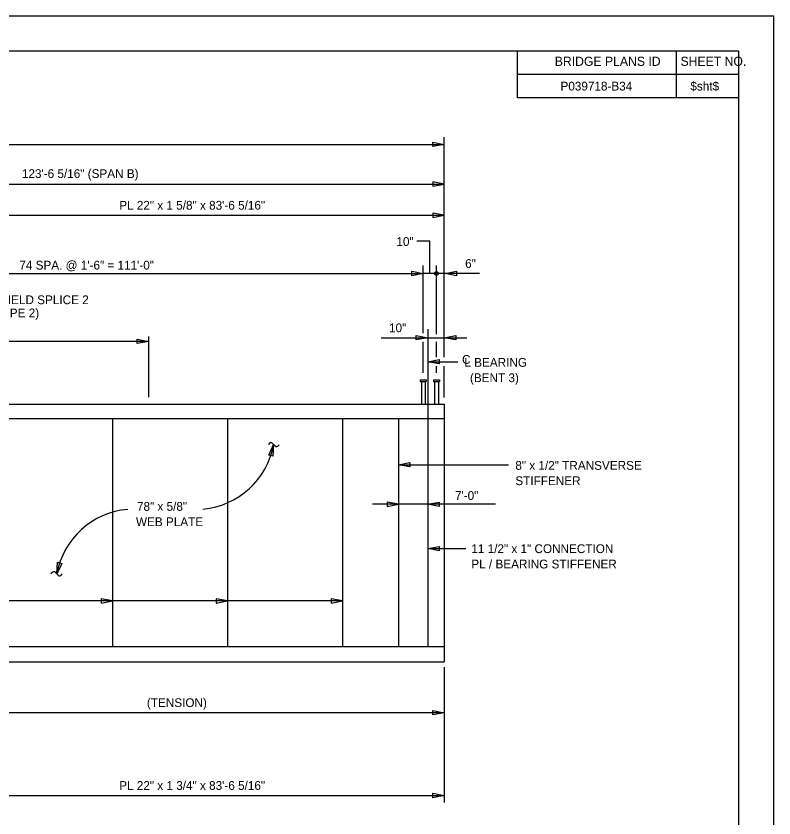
# Model space of a CAD drawing. Extents: x -383 to 7, y -330 to -94.
# Drawn here: x -204.36 to -161.18, y -145.18 to -99.49 of the extents above; entities that cross this region are included whole.
import ezdxf

# ---------------------------------------------------------------- set-up
doc = ezdxf.new("R2010")
doc.units = 0
for name, color, linetype in [('BR_AUTO DIMENSION', 7, 'Continuous'), ('BR_BORDER LINES', 7, 'Continuous'), ('BR_CENTER LINES', 7, 'Continuous'), ('BR_STRUCTURAL STEEL', 7, 'Continuous'), ('BR_TEXT', 7, 'Continuous'), ('Default', 7, 'Continuous'), ('Level 31', 7, 'Continuous')]:
    doc.layers.add(name, color=color, linetype=linetype)

msp = doc.modelspace()

# ---------------------------------------------------------------- linework, layer by layer
at = {"layer": 'BR_AUTO DIMENSION'}
for p, q in [((-179.96, -118.929), (-179.96, -106.393)), ((-276.288, -106.806), (-179.96, -106.806)), ((-221.135, -109.064), (-179.96, -109.064)), ((-207.802, -110.841), (-179.96, -110.841)), ((-181.155, -117.562), (-181.155, -113.71)), ((-180.405, -117.621), (-180.405, -113.71)), ((-217.404, -114.159), (-181.155, -114.159)), ((-177.951, -114.159), (-181.155, -114.159)), ((-196.802, -117.738), (-196.802, -121.213)), ((-183.559, -117.821), (-178.682, -117.821)), ((-196.802, -118.028), (-221.135, -118.028)), ((-181.155, -119.81), (-181.155, -118.048)), ((-180.405, -118.929), (-180.405, -118.048)), ((-180.905, -119.183), (-179.181, -119.183)), ((-180.405, -119.81), (-180.405, -119.447)), ((-179.96, -121.218), (-179.96, -119.447)), ((-182.571, -125.056), (-176.308, -125.056)), ((-177.046, -127.307), (-184.05, -127.307)), ((-180.905, -129.829), (-178.731, -129.829)), ((-185.75, -132.816), (-283.86, -132.816)), ((-179.96, -136.592), (-179.96, -144.298)), ((-179.96, -139.18), (-210.469, -139.18)), ((-207.802, -143.898), (-179.96, -143.898))]:
    msp.add_line(p, q, dxfattribs=at)
for points in [[(-180.61, -106.681), (-179.96, -106.806), (-180.61, -106.931)], [(-180.61, -109.189), (-179.96, -109.064), (-180.61, -108.939)], [(-180.61, -110.966), (-179.96, -110.841), (-180.61, -110.716)], [(-181.805, -114.034), (-181.155, -114.159), (-181.805, -114.284)], [(-179.255, -114.284), (-179.905, -114.159), (-179.255, -114.034)], [(-181.555, -117.696), (-180.905, -117.821), (-181.555, -117.946)], [(-179.31, -117.946), (-179.96, -117.821), (-179.31, -117.696)], [(-197.452, -117.903), (-196.802, -118.028), (-197.452, -118.153)], [(-180.255, -119.308), (-180.905, -119.183), (-180.255, -119.058)], [(-189.964, -124.504), (-189.681, -123.906), (-189.722, -124.566)], [(-181.921, -125.181), (-182.571, -125.056), (-181.921, -124.931)], [(-183.221, -127.432), (-182.571, -127.307), (-183.221, -127.182)], [(-180.255, -127.432), (-180.905, -127.307), (-180.255, -127.182)], [(-180.255, -129.954), (-180.905, -129.829), (-180.255, -129.704)], [(-201.75, -130.673), (-202.032, -131.271), (-201.992, -130.611)], [(-199.514, -132.941), (-198.864, -132.816), (-199.514, -132.691)], [(-192.957, -132.941), (-192.307, -132.816), (-192.957, -132.691)], [(-186.4, -132.941), (-185.75, -132.816), (-186.4, -132.691)], [(-180.61, -139.055), (-179.96, -139.18), (-180.61, -139.305)], [(-180.61, -143.773), (-179.96, -143.898), (-180.61, -144.023)]]:
    msp.add_lwpolyline(points, close=True, dxfattribs=at)
msp.add_lwpolyline([(-180.78, -114.159), (-180.78, -112.317), (-181.52, -112.317)], dxfattribs=at)
msp.add_lwpolyline([(-180.78, -114.159), (-180.78, -112.317), (-181.52, -112.317)], dxfattribs=at)
msp.add_circle((-180.405, -114.159), 0.111, dxfattribs=at)
for centre, start, end in [((-194.106, -123.102), 274.9624, 349.7037), ((-197.608, -132.075), 94.9624, 169.7037)]:
    msp.add_arc(centre, 4.497, start, end, dxfattribs=at)
at = {"layer": 'BR_BORDER LINES'}
for p, q in [((-163.178, -101.489), (-297.843, -101.489)), ((-175.788, -104.156), (-175.788, -101.489)), ((-166.722, -104.156), (-166.722, -101.489)), ((-163.178, -185.489), (-163.178, -101.489)), ((-175.788, -102.808), (-163.178, -102.808)), ((-166.722, -102.808), (-163.178, -102.808)), ((-163.178, -104.156), (-175.788, -104.156))]:
    msp.add_line(p, q, dxfattribs=at)
at = {"layer": 'BR_CENTER LINES'}
msp.add_line((-180.905, -117.333), (-180.905, -122.412), dxfattribs=at)
at = {"layer": 'BR_STRUCTURAL STEEL'}
for p, q in [((-207.802, -121.6), (-179.96, -121.6)), ((-179.96, -121.6), (-179.96, -122.412)), ((-276.288, -122.412), (-179.96, -122.412)), ((-198.864, -122.412), (-198.864, -135.412)), ((-192.307, -122.412), (-192.307, -135.412)), ((-185.75, -122.412), (-185.75, -135.412)), ((-182.571, -122.412), (-182.571, -135.412)), ((-180.905, -122.412), (-180.905, -135.412)), ((-179.96, -122.412), (-179.96, -135.412)), ((-276.288, -135.412), (-179.96, -135.412)), ((-179.96, -135.412), (-179.96, -136.287)), ((-207.802, -136.287), (-179.96, -136.287))]:
    msp.add_line(p, q, dxfattribs=at)
at = {"layer": 'BR_TEXT'}
for p, q in [((-189.941, -123.853), (-189.983, -123.914)), ((-189.6, -123.98), (-189.763, -123.831)), ((-189.366, -123.914), (-189.396, -123.96)), ((-202.347, -131.263), (-202.318, -131.217)), ((-202.114, -131.197), (-201.951, -131.346)), ((-201.772, -131.324), (-201.73, -131.263))]:
    msp.add_line(p, q, dxfattribs=at)
for centre, radius, start, end in [((-189.843, -123.906), 0.111, 43.4519, 151.7375), ((-189.506, -123.899), 0.125, 221.007, 330.8059), ((-202.208, -131.278), 0.125, 41.007, 150.8059), ((-201.87, -131.271), 0.111, 223.4519, 331.7375)]:
    msp.add_arc(centre, radius, start, end, dxfattribs=at)
at = {"layer": 'Default'}
for p, q in [((-181.326, -120.225), (-181.326, -120.319)), ((-181.326, -120.225), (-180.983, -120.225)), ((-181.326, -120.319), (-180.983, -120.319)), ((-181.264, -120.319), (-181.264, -121.6)), ((-181.045, -120.319), (-181.045, -121.6)), ((-180.983, -120.225), (-180.983, -120.319)), ((-180.576, -120.225), (-180.576, -120.319)), ((-180.576, -120.225), (-180.233, -120.225)), ((-180.576, -120.319), (-180.233, -120.319)), ((-180.514, -120.319), (-180.514, -121.6)), ((-180.295, -120.319), (-180.295, -121.6)), ((-180.233, -120.225), (-180.233, -120.319))]:
    msp.add_line(p, q, dxfattribs=at)
at = {"layer": 'Level 31'}
msp.add_lwpolyline([(-305.176, -187.489), (-161.176, -187.489), (-161.176, -99.489), (-305.176, -99.489)], close=True, dxfattribs=at)

# ---------------------------------------------------------------- texts
at = {"layer": 'BR_AUTO DIMENSION'}
for s, p in [('123\'-6 5/16" (SPAN B)', (-204.023, -108.717)), ('PL 22" x 1 5/8" x 83\'-6 5/16"', (-198.479, -110.522)), ('10"', (-182.686, -112.585)), ('74 SPA. @ 1\'-6" = 111\'-0"', (-204.171, -113.933)), ('6"', (-178.77, -113.839)), ('10"', (-183.107, -117.502)), ('78" x 5/8" ', (-197.467, -127.678)), ('WEB PLATE', (-197.525, -128.553)), ('(TENSION)', (-196.901, -138.86)), ('PL 22" x 1 3/4" x 83\'-6 5/16"', (-198.479, -143.579))]:
    msp.add_text(s, height=0.5, rotation=360, dxfattribs=at).set_placement(p)
msp.add_text('7\'-0"', height=0.5, dxfattribs=at).set_placement((-179.349, -127.057))
at = {"layer": 'BR_TEXT'}
for s, height, p in [('BRIDGE PLANS ID', 0.52, (-173.663, -102.327)), ('SHEET NO.', 0.52, (-166.499, -102.327)), ('P039718-B34', 0.5, (-173.338, -103.732)), ('$sht$', 0.5, (-165.939, -103.732)), ('C', 0.5, (-178.946, -119.306)), ('L BEARING', 0.5, (-178.813, -119.473)), ('(BENT 3)', 0.5, (-178.495, -120.348)), ('11 1/2" x 1" CONNECTION ', 0.5, (-178.417, -130.086)), ('PL / BEARING STIFFENER', 0.5, (-178.417, -130.961))]:
    msp.add_text(s, height=height, dxfattribs=at).set_placement(p)
for s, p in [('L FIELD SPLICE 2', (-205.79, -115.905)), ('(TYPE 2)', (-205.79, -116.655)), ('8" x 1/2" TRANSVERSE', (-175.909, -125.341)), ('STIFFENER', (-175.909, -126.216))]:
    msp.add_text(s, height=0.5, rotation=360, dxfattribs=at).set_placement(p)

doc.saveas('drawing.dxf')
